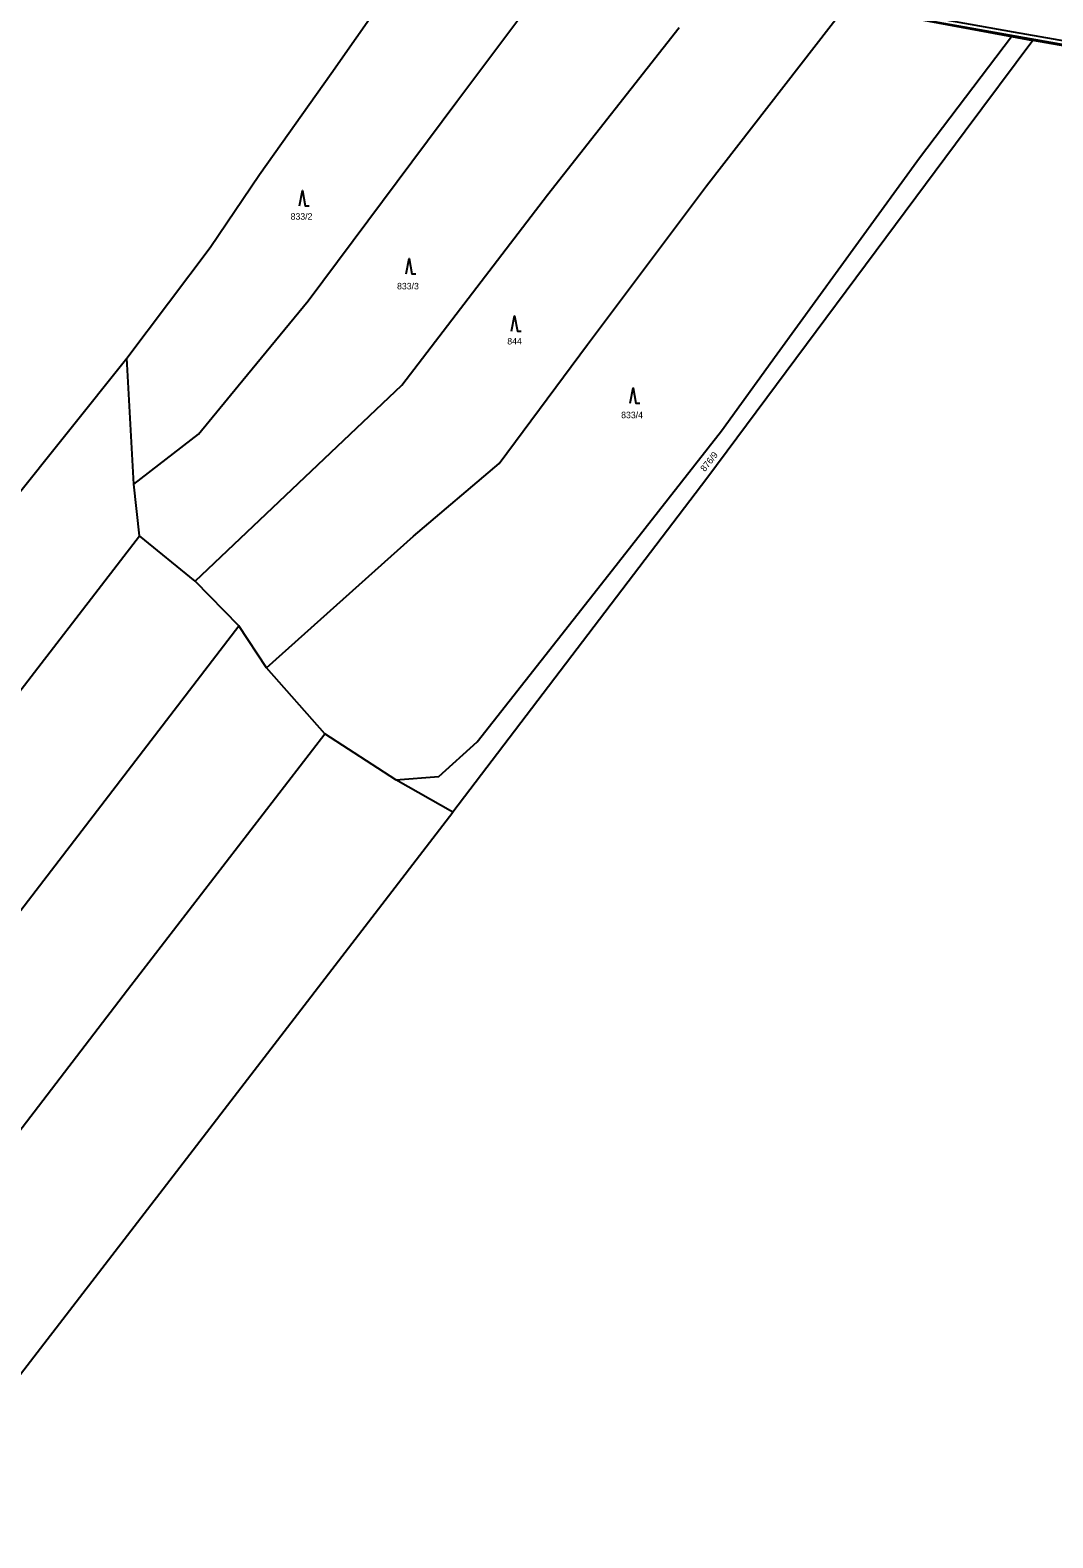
# Model space of a CAD drawing. Extents: x -749173 to -746119, y -1132678 to -1130338.
# Drawn here: x -747979.1 to -747712.1, y -1132264.1 to -1131870.4 of the extents above; entities that cross this region are included whole.
import ezdxf

# ---------------------------------------------------------------- set-up
doc = ezdxf.new("R2010")
doc.units = 0
for name, color, linetype in [('Vrstva 1', 7, 'Continuous'), ('Vrstva 18', 7, 'Continuous'), ('Vrstva 25', 7, 'Continuous'), ('Vrstva 4', 7, 'Continuous'), ('Vrstva 52', 7, 'Continuous')]:
    doc.layers.add(name, color=color, linetype=linetype)

msp = doc.modelspace()

# ---------------------------------------------------------------- linework, layer by layer
at = {"layer": 'Vrstva 1'}
for points in [[(-747867.67, -1131889.02), (-747839.53, -1131851.31)], [(-747900.51, -1131881.74), (-747887.43, -1131863.05)], [(-747802.54, -1131911.01), (-747766.02, -1131864.03)], [(-747766.02, -1131864.03), (-747722.87, -1131872.02)], [(-747844.01, -1131913.39), (-747809.7, -1131869.69)], [(-747746.88, -1131903.75), (-747722.87, -1131872.02)], [(-747722.87, -1131872.02), (-747717.34, -1131873.06)], [(-747717.34, -1131873.06), (-747734.99, -1131896.78)], [(-747681.55, -1131879.32), (-747717.34, -1131873.06)], [(-747919.22, -1131908.11), (-747900.51, -1131881.74)], [(-747906.51, -1131941.09), (-747867.67, -1131889.02)], [(-747734.99, -1131896.78), (-747802.48, -1131987.42)], [(-747784.06, -1131954.95), (-747746.88, -1131903.75)], [(-747932.14, -1131927.11), (-747919.22, -1131908.11)], [(-747833.59, -1131952.47), (-747802.54, -1131911.01)], [(-747882.05, -1131963.13), (-747844.01, -1131913.39)], [(-747953.85, -1131956.03), (-747932.14, -1131927.11)], [(-747924.81, -1131963.24), (-747906.51, -1131941.09)], [(-747856.68, -1131983.56), (-747833.59, -1131952.47)], [(-747798.57, -1131974.98), (-747784.06, -1131954.95)], [(-747999.61, -1132013.23), (-747953.85, -1131956.03)], [(-747952, -1131988.9), (-747953.85, -1131956.03)], [(-747936.01, -1132014.3), (-747882.05, -1131963.13)], [(-747935.13, -1131975.9), (-747924.81, -1131963.24)], [(-747828.94, -1132013.76), (-747798.57, -1131974.98)], [(-747952, -1131988.9), (-747935.13, -1131975.9)], [(-747878.99, -1132002.51), (-747856.68, -1131983.56)], [(-747950.56, -1132002.45), (-747952, -1131988.9)], [(-747802.48, -1131987.42), (-747868.72, -1132074.63)], [(-748027.05, -1132101.68), (-747950.56, -1132002.45)], [(-747936.01, -1132014.3), (-747950.56, -1132002.45)], [(-747917.43, -1132036.91), (-747878.99, -1132002.51)], [(-747924.61, -1132025.96), (-747936.01, -1132014.3)], [(-747862.43, -1132056.26), (-747828.94, -1132013.76)], [(-747997.64, -1132121.05), (-747924.61, -1132025.96)], [(-747917.43, -1132036.91), (-747924.61, -1132025.96)], [(-747902.2, -1132054.13), (-747917.43, -1132036.91)], [(-747953.69, -1132120.95), (-747902.2, -1132054.13)], [(-747883.62, -1132066.11), (-747902.2, -1132054.13)], [(-747872.44, -1132065.32), (-747862.43, -1132056.26)], [(-747883.62, -1132066.11), (-747872.44, -1132065.32)], [(-747868.72, -1132074.63), (-747883.62, -1132066.11)], [(-747941.76, -1132169.56), (-747868.72, -1132074.63)], [(-747983.42, -1132159.94), (-747953.69, -1132120.95)], [(-748014.63, -1132264.1), (-747941.76, -1132169.56)]]:
    msp.add_lwpolyline(points, dxfattribs=at)
at = {"layer": 'Vrstva 25'}
for points in [[(-747908.76, -1131916.22), (-747908.01, -1131912.22), (-747907.26, -1131916.22), (-747906.26, -1131916.22)], [(-747880.91, -1131934), (-747880.16, -1131930), (-747879.41, -1131934), (-747878.41, -1131934)], [(-747853.39, -1131948.98), (-747852.64, -1131944.98), (-747851.89, -1131948.98), (-747850.89, -1131948.98)], [(-747822.44, -1131967.75), (-747821.69, -1131963.75), (-747820.94, -1131967.75), (-747819.94, -1131967.75)]]:
    msp.add_lwpolyline(points, dxfattribs=at)
at = {"layer": 'Vrstva 4'}
for points in [[(-747722.34, -1131870.9), (-747838.66, -1131850.12)], [(-747681.16, -1131878.17), (-747722.34, -1131870.9)]]:
    msp.add_lwpolyline(points, dxfattribs=at)
at = {"layer": 'Vrstva 52'}
msp.add_lwpolyline([(-747981.19, -1131822.75), (-747967.99, -1131825.11), (-747965.94, -1131825.48), (-747945.5, -1131829.12), (-747888.94, -1131839.37), (-747885.06, -1131840.12), (-747879.56, -1131841.5), (-747791.94, -1131859.37), (-747767.72, -1131863.73), (-747766.03, -1131864.04), (-747763.74, -1131864.45), (-747752.37, -1131866.5), (-747687.75, -1131878), (-747689.72, -1131868.02), (-747690.68, -1131863.17), (-747691.19, -1131860.62), (-747690.58, -1131855.27), (-747690.31, -1131852.87), (-747681.37, -1131842.25), (-747607.37, -1131769.12)], dxfattribs=at)

# ---------------------------------------------------------------- texts
at = {"layer": 'Vrstva 18'}
for s, p in [('833/2', (-747911.09, -1131919.88)), ('833/3', (-747883.31, -1131938.08)), ('844', (-747854.53, -1131952.46)), ('833/4', (-747824.8, -1131971.72))]:
    msp.add_text(s, height=1.7, dxfattribs=at).set_placement(p)
msp.add_text('876/9', height=1.7, rotation=51.698, dxfattribs=at).set_placement((-747802.95, -1131985.81))

doc.saveas('drawing.dxf')
